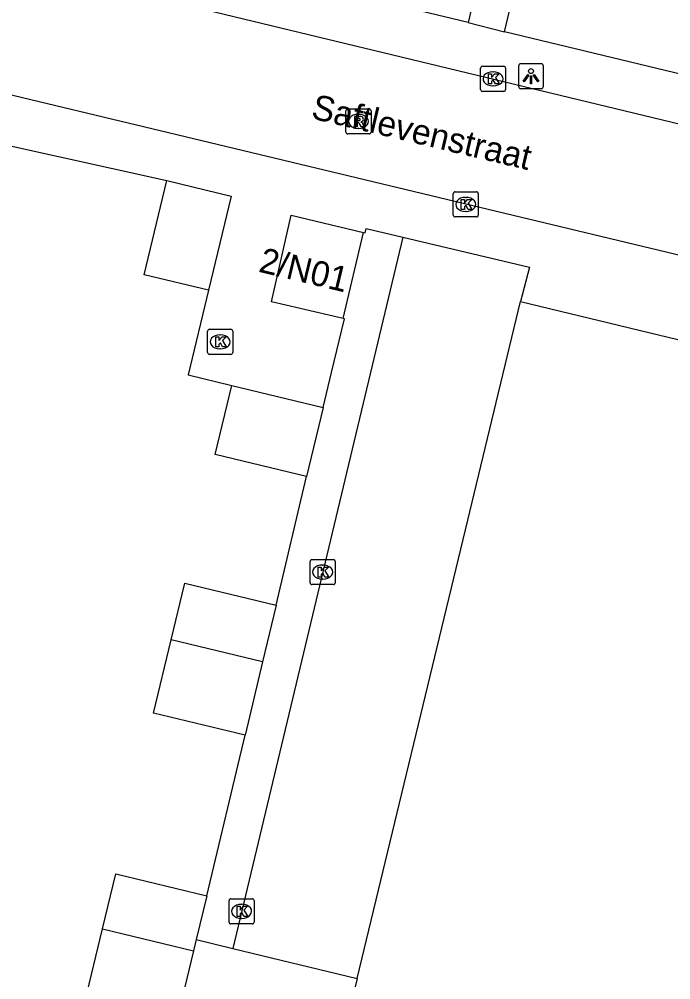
# Model space of a CAD drawing. Extents: x 162812 to 163818, y 381639 to 382470.
# Drawn here: x 163451.04 to 163477.02, y 382165.81 to 382204.11 of the extents above; entities that cross this region are included whole.
import ezdxf

# ---------------------------------------------------------------- set-up
doc = ezdxf.new("R2010")
doc.units = 0
for name, color, linetype in [('IMGEO_Kolk', 7, 'Continuous'), ('IMGEO_Lichtpunt', 7, 'Continuous'), ('IMGEO_Openbare_ruimte_label', 7, 'Continuous'), ('IMGEO_Pand', 7, 'Continuous'), ('IMGEO_Pand_nummerreeks', 7, 'Continuous'), ('IMGEO_Rijbaan_lokaal_open', 7, 'Continuous'), ('IMGEO_Rioolput', 7, 'Continuous'), ('IMGEO_Voetpad_open', 7, 'Continuous')]:
    doc.layers.add(name, color=color, linetype=linetype)

msp = doc.modelspace()

# ---------------------------------------------------------------- linework, layer by layer
at = {"layer": 'IMGEO_Kolk'}
for p, q in [((163469.429, 382201.302), (163469.429, 382202.154)), ((163469.504, 382202.228), (163470.356, 382202.228)), ((163470.43, 382202.154), (163470.43, 382201.302)), ((163469.917, 382202.008), (163469.942, 382202.008)), ((163469.94, 382201.448), (163469.915, 382201.448)), ((163470.356, 382201.228), (163469.504, 382201.228)), ((163468.341, 382196.298), (163468.341, 382197.15)), ((163468.416, 382197.224), (163469.268, 382197.224)), ((163469.342, 382197.15), (163469.342, 382196.298)), ((163468.829, 382197.004), (163468.854, 382197.004)), ((163468.852, 382196.444), (163468.827, 382196.444)), ((163469.268, 382196.224), (163468.416, 382196.224)), ((163458.551, 382190.817), (163458.551, 382191.669)), ((163458.626, 382191.743), (163459.478, 382191.743)), ((163459.039, 382191.523), (163459.064, 382191.523)), ((163459.552, 382191.669), (163459.552, 382190.817)), ((163459.478, 382190.743), (163458.626, 382190.743)), ((163459.062, 382190.963), (163459.037, 382190.963)), ((163462.636, 382181.639), (163462.636, 382182.491)), ((163462.711, 382182.565), (163463.563, 382182.565)), ((163463.124, 382182.345), (163463.149, 382182.345)), ((163463.637, 382182.491), (163463.637, 382181.639)), ((163463.563, 382181.565), (163462.711, 382181.565)), ((163463.147, 382181.785), (163463.122, 382181.785)), ((163459.404, 382168.113), (163459.404, 382168.965)), ((163459.479, 382169.039), (163460.331, 382169.039)), ((163459.892, 382168.819), (163459.917, 382168.819)), ((163460.405, 382168.965), (163460.405, 382168.113)), ((163460.331, 382168.039), (163459.479, 382168.039)), ((163459.915, 382168.259), (163459.89, 382168.259))]:
    msp.add_line(p, q, dxfattribs=at)
for points in [[(163469.429, 382201.302), (163469.429, 382202.154)], [(163469.504, 382202.228), (163470.356, 382202.228)], [(163470.43, 382202.154), (163470.43, 382201.302)], [(163469.75, 382201.928), (163469.873, 382201.928), (163469.873, 382201.777), (163470.003, 382201.928), (163470.167, 382201.928), (163470.021, 382201.777), (163470.174, 382201.528), (163470.022, 382201.528), (163469.937, 382201.692), (163469.873, 382201.625), (163469.873, 382201.528), (163469.75, 382201.528), (163469.75, 382201.928)], [(163470.356, 382201.228), (163469.504, 382201.228)], [(163468.341, 382196.298), (163468.341, 382197.15)], [(163468.416, 382197.224), (163469.268, 382197.224)], [(163469.342, 382197.15), (163469.342, 382196.298)], [(163468.662, 382196.924), (163468.785, 382196.924), (163468.785, 382196.773), (163468.915, 382196.924), (163469.079, 382196.924), (163468.933, 382196.773), (163469.086, 382196.524), (163468.934, 382196.524), (163468.849, 382196.688), (163468.785, 382196.621), (163468.785, 382196.524), (163468.662, 382196.524), (163468.662, 382196.924)], [(163469.268, 382196.224), (163468.416, 382196.224)], [(163458.551, 382190.817), (163458.551, 382191.669)], [(163458.626, 382191.743), (163459.478, 382191.743)], [(163458.872, 382191.443), (163458.995, 382191.443), (163458.995, 382191.292), (163459.125, 382191.443), (163459.289, 382191.443), (163459.143, 382191.292), (163459.296, 382191.043), (163459.144, 382191.043), (163459.059, 382191.207), (163458.995, 382191.14), (163458.995, 382191.043), (163458.872, 382191.043), (163458.872, 382191.443)], [(163459.552, 382191.669), (163459.552, 382190.817)], [(163459.478, 382190.743), (163458.626, 382190.743)], [(163462.636, 382181.639), (163462.636, 382182.491)], [(163462.711, 382182.565), (163463.563, 382182.565)], [(163462.957, 382182.265), (163463.08, 382182.265), (163463.08, 382182.114), (163463.21, 382182.265), (163463.374, 382182.265), (163463.228, 382182.114), (163463.381, 382181.865), (163463.229, 382181.865), (163463.144, 382182.029), (163463.08, 382181.962), (163463.08, 382181.865), (163462.957, 382181.865), (163462.957, 382182.265)], [(163463.637, 382182.491), (163463.637, 382181.639)], [(163463.563, 382181.565), (163462.711, 382181.565)], [(163459.404, 382168.113), (163459.404, 382168.965)], [(163459.479, 382169.039), (163460.331, 382169.039)], [(163460.405, 382168.965), (163460.405, 382168.113)], [(163459.725, 382168.739), (163459.848, 382168.739), (163459.848, 382168.588), (163459.978, 382168.739), (163460.142, 382168.739), (163459.996, 382168.588), (163460.149, 382168.339), (163459.997, 382168.339), (163459.912, 382168.503), (163459.848, 382168.436), (163459.848, 382168.339), (163459.725, 382168.339), (163459.725, 382168.739)], [(163460.331, 382168.039), (163459.479, 382168.039)]]:
    msp.add_lwpolyline(points, dxfattribs=at)
for centre, start, end in [((163469.506, 382202.152), 91.552, 178.448), ((163469.506, 382202.152), 91.552, 178.448), ((163470.354, 382202.152), 1.552, 88.448), ((163470.354, 382202.152), 1.552, 88.448), ((163469.506, 382201.304), 181.552, 268.448), ((163469.506, 382201.304), 181.552, 268.448), ((163470.354, 382201.304), 271.552, 358.448), ((163470.354, 382201.304), 271.552, 358.448), ((163468.418, 382197.148), 91.552, 178.448), ((163468.418, 382197.148), 91.552, 178.448), ((163469.266, 382197.148), 1.552, 88.448), ((163469.266, 382197.148), 1.552, 88.448), ((163468.418, 382196.3), 181.552, 268.448), ((163468.418, 382196.3), 181.552, 268.448), ((163469.266, 382196.3), 271.552, 358.448), ((163469.266, 382196.3), 271.552, 358.448), ((163458.628, 382191.667), 91.552, 178.448), ((163458.628, 382191.667), 91.552, 178.448), ((163459.476, 382191.667), 1.552, 88.448), ((163459.476, 382191.667), 1.552, 88.448), ((163458.628, 382190.819), 181.552, 268.448), ((163458.628, 382190.819), 181.552, 268.448), ((163459.476, 382190.819), 271.552, 358.448), ((163459.476, 382190.819), 271.552, 358.448), ((163462.713, 382182.489), 91.552, 178.448), ((163462.713, 382182.489), 91.552, 178.448), ((163463.561, 382182.489), 1.552, 88.448), ((163463.561, 382182.489), 1.552, 88.448), ((163462.713, 382181.641), 181.552, 268.448), ((163462.713, 382181.641), 181.552, 268.448), ((163463.561, 382181.641), 271.552, 358.448), ((163463.561, 382181.641), 271.552, 358.448), ((163459.481, 382168.963), 91.552, 178.448), ((163459.481, 382168.963), 91.552, 178.448), ((163460.329, 382168.963), 1.552, 88.448), ((163460.329, 382168.963), 1.552, 88.448), ((163459.481, 382168.115), 181.552, 268.448), ((163459.481, 382168.115), 181.552, 268.448), ((163460.329, 382168.115), 271.552, 358.448), ((163460.329, 382168.115), 271.552, 358.448)]:
    msp.add_arc(centre, 0.0765, start, end, dxfattribs=at)
for centre, major_axis, ratio, start_param, end_param in [((163469.916, 382201.728), (-0.387, 0.002), 0.722429, 4.712389, 7.853982), ((163469.941, 382201.728), (-0.39, 0.002), 0.717154, 1.570796, 4.712389), ((163468.828, 382196.724), (-0.387, 0.002), 0.722429, 4.712389, 7.853982), ((163468.853, 382196.724), (-0.39, 0.002), 0.717154, 1.570796, 4.712389), ((163459.038, 382191.243), (-0.387, 0.002), 0.722429, 4.712389, 7.853982), ((163459.063, 382191.243), (-0.39, 0.002), 0.717154, 1.570796, 4.712389), ((163463.123, 382182.065), (-0.387, 0.002), 0.722429, 4.712389, 7.853982), ((163463.148, 382182.065), (-0.39, 0.002), 0.717154, 1.570796, 4.712389), ((163459.891, 382168.539), (-0.387, 0.002), 0.722429, 4.712389, 7.853982), ((163459.916, 382168.539), (-0.39, 0.002), 0.717154, 1.570796, 4.712389)]:
    msp.add_ellipse(centre, major_axis=major_axis, ratio=ratio, start_param=start_param, end_param=end_param, dxfattribs=at)
at = {"layer": 'IMGEO_Lichtpunt'}
for p, q in [((163470.944, 382202.238), (163470.944, 382201.431)), ((163470.944, 382202.238), (163470.944, 382201.431)), ((163471.846, 382202.333), (163471.038, 382202.333)), ((163471.846, 382202.333), (163471.038, 382202.333)), ((163471.94, 382201.431), (163471.94, 382202.238)), ((163471.94, 382201.431), (163471.94, 382202.238)), ((163471.038, 382201.337), (163471.846, 382201.337)), ((163471.038, 382201.337), (163471.846, 382201.337))]:
    msp.add_line(p, q, dxfattribs=at)
for points in [[(163471.318, 382201.902), (163471.357, 382201.874), (163471.169, 382201.612), (163471.131, 382201.639), (163471.318, 382201.902)], [(163471.42, 382201.854), (163471.467, 382201.854), (163471.467, 382201.532), (163471.42, 382201.532), (163471.42, 382201.854)], [(163471.53, 382201.874), (163471.568, 382201.901), (163471.755, 382201.639), (163471.716, 382201.611), (163471.53, 382201.874)]]:
    msp.add_lwpolyline(points, dxfattribs=at)
msp.add_circle((163471.443, 382202.036), 0.0994, dxfattribs=at)
for centre, start, end in [((163471.038, 382202.238), 90, 180), ((163471.038, 382202.238), 90, 180), ((163471.846, 382202.238), 0, 90), ((163471.846, 382202.238), 0, 90), ((163471.038, 382201.431), 180, 270), ((163471.038, 382201.431), 180, 270), ((163471.846, 382201.431), 270, 0), ((163471.846, 382201.431), 270, 360)]:
    msp.add_arc(centre, 0.0946, start, end, dxfattribs=at)
at = {"layer": 'IMGEO_Pand'}
for points in [[(163455.726, 382207.151), (163456.946, 382212.235), (163470.152, 382209.066), (163468.932, 382203.981)], [(163470.382, 382203.596), (163471.6, 382208.672), (163484.806, 382205.503), (163483.588, 382200.427)], [(163468.932, 382203.981), (163455.726, 382207.151)], [(163483.588, 382200.427), (163470.382, 382203.596)], [(163458.588, 382193.303), (163456.021, 382193.921), (163456.925, 382197.671)], [(163456.925, 382197.671), (163459.492, 382197.053), (163458.588, 382193.303)], [(163463.951, 382192.176), (163461.092, 382192.838), (163461.881, 382196.295), (163464.762, 382195.604)], [(163463.951, 382192.176), (163464.762, 382195.604)], [(163464.518, 382165.864), (163468.827, 382183.755), (163471.018, 382192.85)], [(163471.018, 382192.85), (163481.258, 382190.383), (163481.58, 382191.719), (163484.757, 382190.954), (163484.443, 382189.652), (163492.2, 382187.783)], [(163462.495, 382185.873), (163458.848, 382186.751), (163459.512, 382189.508)], [(163459.512, 382189.508), (163463.159, 382188.63)], [(163463.159, 382188.63), (163462.495, 382185.873)], [(163457.101, 382179.362), (163457.645, 382181.62), (163461.288, 382180.742)], [(163461.288, 382180.742), (163460.744, 382178.484)], [(163460.042, 382175.566), (163456.398, 382176.444), (163457.101, 382179.362)], [(163460.744, 382178.484), (163457.101, 382179.362)], [(163460.744, 382178.484), (163460.042, 382175.566)], [(163454.359, 382167.837), (163454.888, 382170.032), (163458.513, 382169.159)], [(163458.513, 382169.159), (163458.093, 382167.414)], [(163457.28, 382164.042), (163453.655, 382164.915), (163454.359, 382167.837)], [(163454.359, 382167.837), (163457.984, 382166.964)], [(163458.093, 382167.414), (163457.984, 382166.964)], [(163457.984, 382166.964), (163457.28, 382164.042)], [(163464.518, 382165.864), (163462.446, 382157.262)]]:
    msp.add_lwpolyline(points, dxfattribs=at)
at = {"layer": 'IMGEO_Rijbaan_lokaal_open'}
for points in [[(163441.975, 382208.454), (163442.296, 382208.377), (163445.466, 382207.633), (163485.228, 382198.029)], [(163484.034, 382193.087), (163443.009, 382202.918), (163440.815, 382203.442)], [(163466.329, 382195.419), (163459.552, 382167.063)], [(163466.329, 382195.419), (163471.381, 382194.218), (163471.018, 382192.85)], [(163458.093, 382167.414), (163459.552, 382167.063)], [(163459.552, 382167.063), (163464.518, 382165.864)]]:
    msp.add_lwpolyline(points, dxfattribs=at)
at = {"layer": 'IMGEO_Rioolput'}
for p, q in [((163464.064, 382199.605), (163464.064, 382200.457)), ((163464.139, 382200.531), (163464.991, 382200.531)), ((163464.552, 382200.311), (163464.577, 382200.311)), ((163465.065, 382200.457), (163465.065, 382199.605)), ((163464.991, 382199.531), (163464.139, 382199.531)), ((163464.575, 382199.751), (163464.55, 382199.751))]:
    msp.add_line(p, q, dxfattribs=at)
for points in [[(163464.064, 382199.605), (163464.064, 382200.457)], [(163464.139, 382200.531), (163464.991, 382200.531)], [(163464.653, 382200.229), (163464.401, 382200.231), (163464.401, 382199.831)], [(163465.065, 382200.457), (163465.065, 382199.605)], [(163464.401, 382199.831), (163464.525, 382199.831), (163464.525, 382199.993), (163464.536, 382199.993)], [(163464.579, 382200.15), (163464.525, 382200.15), (163464.525, 382200.069)], [(163464.525, 382200.069), (163464.577, 382200.069)], [(163464.583, 382199.964), (163464.654, 382199.831), (163464.794, 382199.831), (163464.729, 382199.957)], [(163464.991, 382199.531), (163464.139, 382199.531)]]:
    msp.add_lwpolyline(points, dxfattribs=at)
for centre, radius, start, end in [((163464.141, 382200.455), 0.0765, 91.552, 178.448), ((163464.141, 382200.455), 0.0765, 91.552, 178.448), ((163464.652, 382200.119), 0.109, 350.3612, 89.416), ((163464.989, 382200.455), 0.0765, 1.552, 88.448), ((163464.989, 382200.455), 0.0765, 1.552, 88.448), ((163464.535, 382199.94), 0.0533, 26.0293, 88.6989), ((163464.561, 382200.258), 0.19, 274.7715, 282.9687), ((163464.585, 382200.054), 0.0964, 77.0061, 93.1865), ((163464.599, 382200.111), 0.0378, 276.6634, 79.6772), ((163464.65, 382200.119), 0.112, 277.5842, 350.9817), ((163464.634, 382199.904), 0.108, 29.5134, 73.7905), ((163464.141, 382199.607), 0.0765, 181.552, 268.448), ((163464.141, 382199.607), 0.0765, 181.552, 268.448), ((163464.989, 382199.607), 0.0765, 271.552, 358.448), ((163464.989, 382199.607), 0.0765, 271.552, 358.448)]:
    msp.add_arc(centre, radius, start, end, dxfattribs=at)
for centre, major_axis, ratio, start_param, end_param in [((163464.551, 382200.031), (-0.387, 0.002), 0.722429, 4.712389, 7.853982), ((163464.576, 382200.031), (-0.39, 0.002), 0.717154, 1.570796, 4.712389)]:
    msp.add_ellipse(centre, major_axis=major_axis, ratio=ratio, start_param=start_param, end_param=end_param, dxfattribs=at)
at = {"layer": 'IMGEO_Voetpad_open'}
for points in [[(163468.932, 382203.981), (163470.382, 382203.596)], [(163450.381, 382199.128), (163456.925, 382197.671)], [(163464.762, 382195.604), (163464.826, 382195.589), (163464.869, 382195.765), (163466.329, 382195.419)], [(163458.588, 382193.303), (163457.774, 382189.926), (163459.512, 382189.508)], [(163463.159, 382188.63), (163463.484, 382190.016), (163464.002, 382192.164), (163463.951, 382192.176)], [(163461.288, 382180.742), (163462.495, 382185.873)], [(163458.513, 382169.159), (163460.042, 382175.566)]]:
    msp.add_lwpolyline(points, dxfattribs=at)

# ---------------------------------------------------------------- texts
at = {"layer": 'IMGEO_Openbare_ruimte_label'}
msp.add_text('Saftlevenstraat', height=1, rotation=346.5889, dxfattribs=at).set_placement((163462.637, 382200.16))
at = {"layer": 'IMGEO_Pand_nummerreeks'}
msp.add_text('2/N01', height=1, rotation=346.5125, dxfattribs=at).set_placement((163460.545, 382194.045))

doc.saveas('drawing.dxf')
